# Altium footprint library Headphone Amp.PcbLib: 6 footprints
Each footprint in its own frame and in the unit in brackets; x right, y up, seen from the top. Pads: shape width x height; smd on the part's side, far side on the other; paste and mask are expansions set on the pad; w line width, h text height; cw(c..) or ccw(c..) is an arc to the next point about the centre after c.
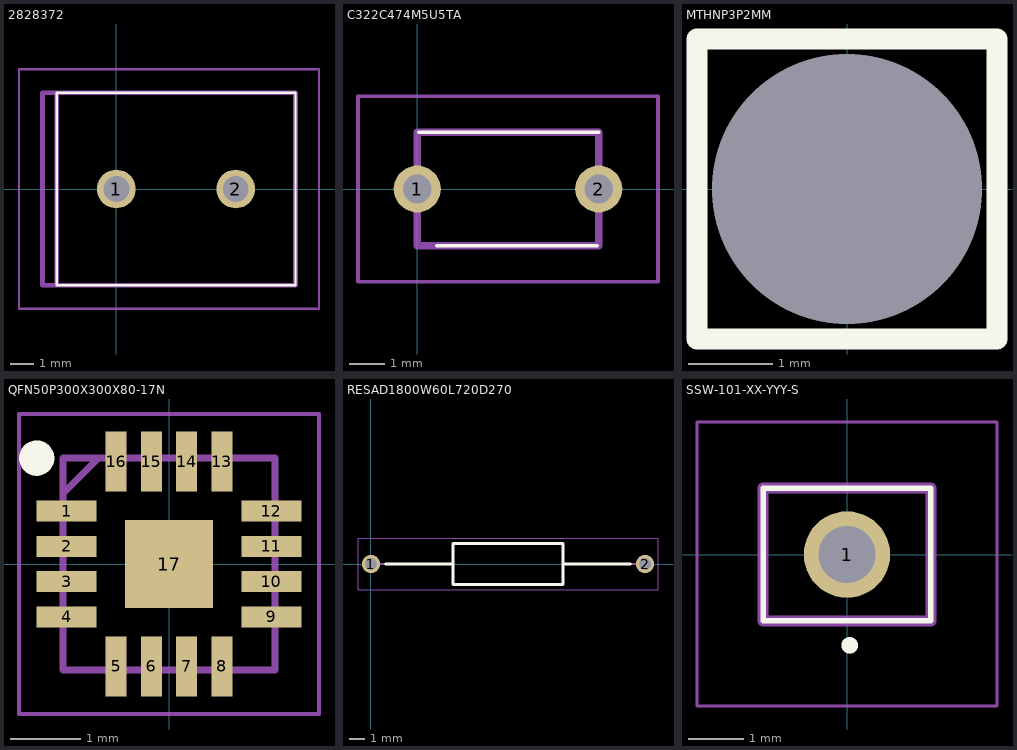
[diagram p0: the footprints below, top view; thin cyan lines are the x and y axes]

## 2828372 [mm]
pads (2):
  round 1.65 hole 1.1: 1(0,0) 2(5.08,0)
Top Overlay:
  lines w0.1: -2.54,-4.1 -2.54,4.1 7.62,4.1 7.62,-4.1 -2.54,-4.1
Mechanical 13:
  lines w0.2: -2.54,-4.1 -3.14,-4.1 -3.14,4.1 -2.54,4.1 ; -2.54,-4.1 -2.54,4.1 ; -2.54,-4.1 -2.54,4.1 ; -2.54,-4.1 7.62,-4.1 7.62,4.1 -2.54,4.1
Mechanical 15:
  lines w0.1: -4.14,-5.1 -4.14,5.1 8.62,5.1 8.62,-5.1 -4.14,-5.1
3D body "282837-2.stp": height 9.84, standoff -3.66, extent -2.51,-4.11 8.25,4.09

## C322C474M5U5TA [mm]
pads (2):
  round 1.316 hole 0.81: 1(0,0) 2(5.08,0)
Top Overlay:
  lines w0.1: 0.04,1.59 5.08,1.59 ; 0.54,-1.59 5.04,-1.59
Mechanical 13:
  lines w0.2: 0,-1.59 0,1.59 5.08,1.59 5.08,-1.59 0,-1.59
Mechanical 15:
  lines w0.1: -1.658,-2.59 -1.658,2.59 6.738,2.59 6.738,-2.59 -1.658,-2.59
3D body "C322C474M5U5TA.stp": height 7.11, standoff -6.49, extent -0.253,-1.595 5.333,1.59

## MTHNP3P2MM [mm] "Mounting Hole Non-Plated 3.2mm"
pads (1):
  round 0 hole 3.2: ""(0,0)
Top Overlay:
  lines w0.254: -1.778,-1.778 -1.778,0.178 -1.778,1.778 0.178,1.778 1.778,1.778 1.778,0.178 1.778,-1.778 0.178,-1.778 -1.778,-1.778

## QFN50P300X300X80-17N [mm]
pads (17):
  rect 0.85x0.3 smd: 1(-1.45,0.75) 2(-1.45,0.25) 3(-1.45,-0.25) 4(-1.45,-0.75) 9(1.45,-0.75) 10(1.45,-0.25) 11(1.45,0.25) 12(1.45,0.75)
  rect 0.3x0.85 smd: 5(-0.75,-1.45) 6(-0.25,-1.45) 7(0.25,-1.45) 8(0.75,-1.45) 13(0.75,1.45) 14(0.25,1.45) 15(-0.25,1.45) 16(-0.75,1.45)
  rect 1.25x1.25 smd: 17(0,0)
Top Overlay:
  circle w0.25: c-1.875,1.5 r0.125
Mechanical 13:
  lines w0.1: -1.5,1 -1,1.5 ; -1.5,-1.5 1.5,-1.5 1.5,1.5 -1.5,1.5 -1.5,-1.5
Mechanical 15:
  lines w0.05: -2.125,-2.125 2.125,-2.125 2.125,2.125 -2.125,2.125 -2.125,-2.125
3D body "MAX97220AETE+T.stp": height 0.8, standoff 0, extent -1.55,-1.55 1.55,1.55

## RESAD1800W60L720D270 [mm]
pads (2):
  round 1.2 hole 0.8: 1(0,0) 2(18,0)
Top Overlay:
  lines w0.2: 0.95,0 5.4,0 ; 12.6,0 17.05,0 ; 5.4,-1.35 5.4,1.35 12.6,1.35 12.6,-1.35 5.4,-1.35
Mechanical 13:
  lines w0.1: 0,0 5.4,0 ; 12.6,0 18,0 ; 5.4,-1.35 5.4,1.35 12.6,1.35 12.6,-1.35 5.4,-1.35
Mechanical 15:
  lines w0.05: -0.85,-1.7 -0.85,1.7 18.85,1.7 18.85,-1.7 -0.85,-1.7
3D body "H8560RFYA.stp": height 2.7, standoff -2.7, extent -0.3,-1.34 18.3,1.34

## SSW-101-XX-YYY-S [mm]
pads (1):
  round 1.57 hole 1.04: 1(0,0)
Top Overlay:
  circle w0.2: c0.05,-1.65 r0.05
  lines w0.1: -1.525,-1.205 1.525,-1.205 1.525,1.205 -1.525,1.205 -1.525,-1.205
Mechanical 13:
  lines w0.2: -1.525,-1.205 1.525,-1.205 1.525,1.205 -1.525,1.205 -1.525,-1.205
Mechanical 15:
  lines w0.05: -2.725,-2.75 2.725,-2.75 2.725,2.405 -2.725,2.405 -2.725,-2.75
